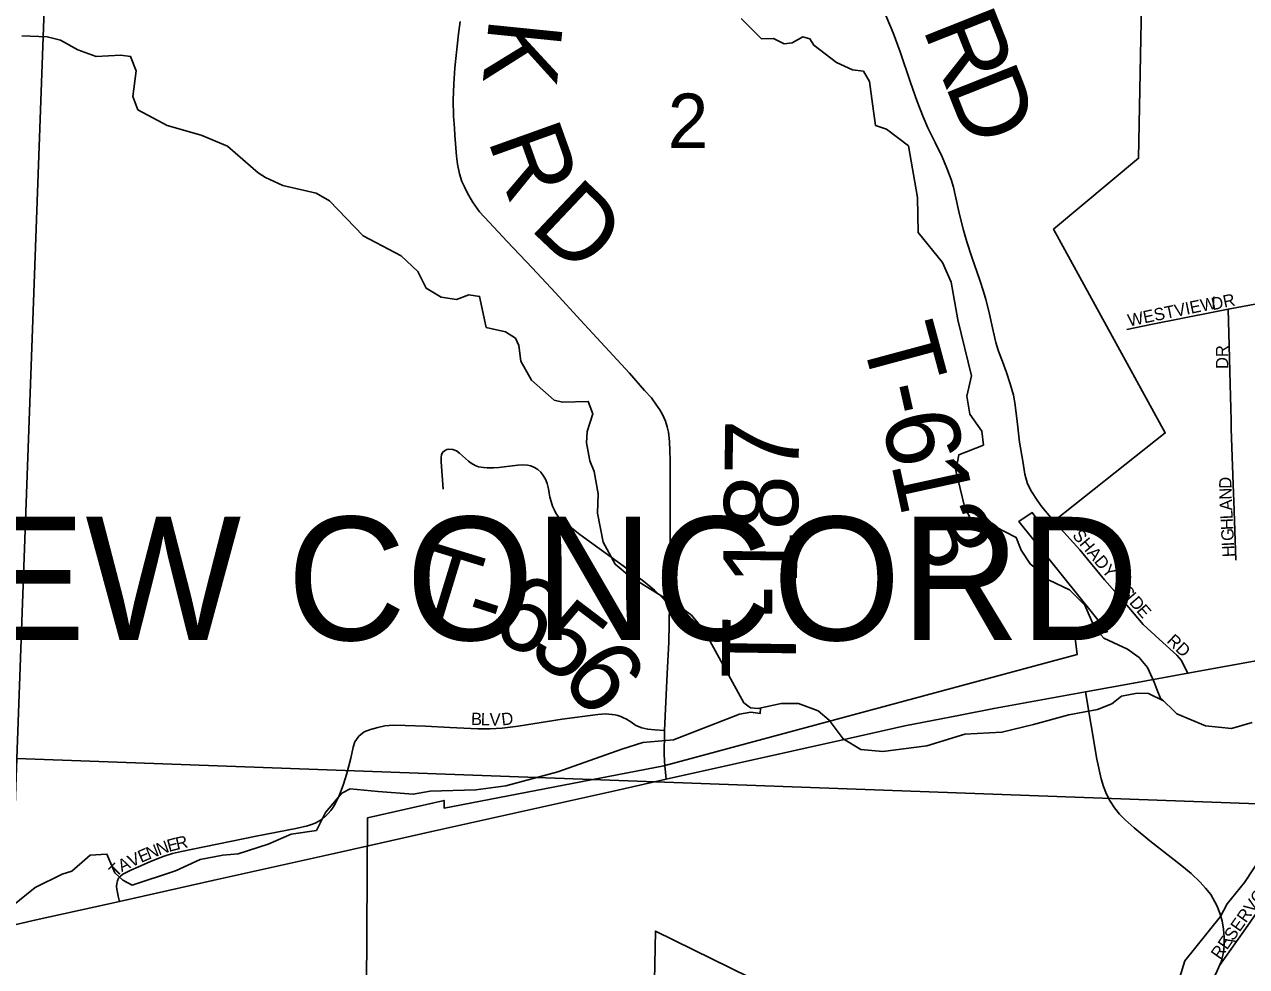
# Model space of a CAD drawing. Extents: x 0 to 34, y 0 to 22.
# Drawn here: x 26.645 to 27.584, y 17.117 to 17.84 of the extents above; entities that cross this region are included whole.
import ezdxf

# ---------------------------------------------------------------- set-up
doc = ezdxf.new("R2010")
doc.units = 0
for name, color, linetype in [('GM_X_City_Street', 7, 'Continuous'), ('GM_X_City_Street_Text', 7, 'Continuous'), ('GM_X_Corporation', 7, 'Continuous'), ('GM_X_Corporation_Text', 7, 'Continuous'), ('GM_X_Minor_River', 7, 'Continuous'), ('GM_X_Section', 7, 'Continuous'), ('GM_X_Section_Text', 7, 'Continuous'), ('GM_X_Township_Road', 7, 'Continuous'), ('GM_X_Township_Road_Text', 7, 'Continuous'), ('GM_X_Township_Subdivision', 7, 'Continuous'), ('GM_X_Township_Subdivision_Text', 7, 'Continuous'), ('GM_X_US_Route', 7, 'Continuous')]:
    doc.layers.add(name, color=color, linetype=linetype)

msp = doc.modelspace()

# ---------------------------------------------------------------- linework, layer by layer
at = {"layer": 'GM_X_City_Street'}
for points in [[(27.56966, 17.62172), (27.58068, 17.62392), (27.60526, 17.62834), (27.63288, 17.63318), (27.64818, 17.63586), (27.6542, 17.63689), (27.68992, 17.64309)], [(27.4918, 17.60613), (27.51017, 17.60988), (27.55923, 17.61963), (27.56966, 17.62172)], [(27.57546, 17.42902), (27.57397, 17.47429), (27.57363, 17.48052), (27.57258, 17.50832), (27.57189, 17.53003), (27.57181, 17.53623), (27.57151, 17.54554), (27.57103, 17.56415), (27.57035, 17.59397), (27.56966, 17.62172)], [(27.53861, 17.34222), (27.5369, 17.34557), (27.53365, 17.35196), (27.53022, 17.35621), (27.51654, 17.3685), (27.50432, 17.37964), (27.4906, 17.39594), (27.47463, 17.41398), (27.45558, 17.43693), (27.43604, 17.45876), (27.43353, 17.46175)], [(27.56653, 17.13793), (27.56654, 17.13955), (27.56598, 17.14584), (27.56483, 17.15205), (27.56316, 17.15814), (27.56084, 17.16405), (27.55787, 17.16964), (27.55614, 17.17229), (27.55228, 17.1773), (27.54804, 17.18196), (27.54119, 17.18843), (27.53396, 17.19442), (27.50936, 17.2136), (27.49734, 17.22344), (27.49044, 17.22965), (27.4862, 17.23411), (27.48233, 17.2389), (27.47895, 17.24399), (27.47618, 17.24946), (27.47396, 17.2552), (27.47217, 17.2611), (27.46863, 17.27622), (27.46011, 17.32793)], [(27.62652, 17.20006), (27.62586, 17.20012), (27.62291, 17.19958), (27.62131, 17.19881), (27.62059, 17.19834), (27.61835, 17.19617), (27.61634, 17.19383), (27.61258, 17.18896), (27.60546, 17.17894), (27.59339, 17.16115), (27.58293, 17.14602), (27.57603, 17.13631)], [(27.56302, 17.11798), (27.56409, 17.12078), (27.565, 17.12383), (27.5657, 17.12693), (27.5662, 17.13006), (27.5665, 17.13322), (27.56653, 17.13793)], [(27.57603, 17.13631), (27.56302, 17.11798)], [(27.56653, 17.13793), (27.57603, 17.13631)], [(27.47295, 16.97658), (27.47573, 16.98116), (27.50327, 17.0227), (27.52697, 17.05934), (27.54391, 17.08549), (27.55559, 17.10394), (27.56024, 17.11211), (27.56302, 17.11798)]]:
    msp.add_lwpolyline(points, dxfattribs=at)
at = {"layer": 'GM_X_Corporation'}
for points in [[(26.90696, 16.92457), (26.90869, 17.23113), (26.9676, 17.24455), (26.96758, 17.23868), (27.13632, 17.27124), (27.45355, 17.35652), (27.45221, 17.36927), (27.4769, 17.37407), (27.40895, 17.45881), (27.41908, 17.4656), (27.42835, 17.45306), (27.5213, 17.52673), (27.43555, 17.68311), (27.50076, 17.73762), (27.50706, 18.06564), (27.60948, 18.06256)], [(26.90696, 16.92457), (26.90869, 17.23113), (26.9676, 17.24455), (26.96758, 17.23868), (27.13632, 17.27124), (27.45355, 17.35652), (27.45221, 17.36927), (27.4769, 17.37407), (27.40895, 17.45881), (27.41908, 17.4656), (27.42835, 17.45306), (27.5213, 17.52673), (27.43555, 17.68311), (27.50076, 17.73762), (27.50706, 18.06564), (27.60948, 18.06256)], [(27.47528, 16.9746), (27.12987, 17.14428), (27.12524, 16.91632)], [(27.47528, 16.9746), (27.12987, 17.14428), (27.12524, 16.91632)]]:
    msp.add_lwpolyline(points, dxfattribs=at)
at = {"layer": 'GM_X_Minor_River'}
for points in [[(27.1957, 17.8449), (27.21128, 17.8294), (27.22037, 17.82946), (27.22873, 17.82534), (27.23479, 17.82614), (27.24309, 17.83074), (27.2484, 17.82926), (27.25147, 17.82435), (27.26898, 17.81118), (27.28113, 17.80557), (27.28947, 17.80448), (27.29407, 17.79654), (27.29646, 17.77949), (27.29884, 17.76282), (27.30719, 17.75983)], [(26.6435, 17.83154), (26.66282, 17.8309), (26.67307, 17.82831), (26.68637, 17.82081), (26.70042, 17.81559), (26.71935, 17.81684), (26.72693, 17.81575), (26.73117, 17.80478), (26.72865, 17.78504), (26.73251, 17.77482), (26.75493, 17.76283), (26.78112, 17.75541), (26.80125, 17.74681), (26.82487, 17.72647), (26.83058, 17.72272), (26.84387, 17.71673), (26.86929, 17.71082), (26.87955, 17.70482), (26.90549, 17.67805), (26.93475, 17.66268), (26.94733, 17.65062), (26.95386, 17.63777), (26.96526, 17.63101), (26.97702, 17.62918), (26.98646, 17.63266), (26.9948, 17.63157), (26.99989, 17.60771), (27.01468, 17.60439), (27.02229, 17.5995), (27.02498, 17.59383), (27.02657, 17.5817), (27.03462, 17.56734), (27.05215, 17.5519), (27.0586, 17.55042), (27.07829, 17.55092), (27.08176, 17.54147), (27.07731, 17.52778), (27.07698, 17.51905), (27.07935, 17.50541), (27.08281, 17.49709), (27.08595, 17.48004), (27.0853, 17.46525), (27.08961, 17.4429), (27.09881, 17.42588), (27.10986, 17.41685), (27.14561, 17.39469), (27.15055, 17.39207), (27.1574, 17.3868), (27.16733, 17.37511), (27.19762, 17.31954), (27.20295, 17.31578), (27.20863, 17.31506), (27.22641, 17.31896), (27.23967, 17.31904), (27.25485, 17.31345), (27.26323, 17.30629), (27.27393, 17.29195), (27.28762, 17.28369), (27.3043, 17.28228)], [(27.30719, 17.75983), (27.32419, 17.74702), (27.33093, 17.70758), (27.33152, 17.68064), (27.35026, 17.65761), (27.35681, 17.64247), (27.36196, 17.61366), (27.37252, 17.57046), (27.36885, 17.55487), (27.37123, 17.54122), (27.38042, 17.528), (27.38164, 17.51738), (27.36275, 17.51003), (27.36057, 17.49787), (27.36722, 17.4702), (27.37261, 17.45923), (27.37792, 17.45851), (27.38472, 17.46084), (27.39045, 17.4548), (27.40681, 17.44657), (27.41067, 17.43673), (27.41757, 17.42615), (27.4252, 17.41975), (27.43207, 17.41372), (27.44766, 17.40624), (27.4595, 17.39456), (27.46721, 17.37677), (27.47409, 17.36923), (27.49234, 17.36063), (27.50111, 17.35424), (27.50761, 17.34669), (27.51262, 17.33534), (27.51494, 17.32928), (27.51725, 17.3236), (27.53023, 17.31117), (27.55228, 17.30183), (27.572, 17.2997), (27.58788, 17.30437)], [(27.3043, 17.28228), (27.3383, 17.28664), (27.36741, 17.29558), (27.39582, 17.29692), (27.42003, 17.30279), (27.44725, 17.3102), (27.4692, 17.31453), (27.48015, 17.31878), (27.48769, 17.32453), (27.4998, 17.3269), (27.50852, 17.32658), (27.52001, 17.32097)], [(27.21042, 17.31545), (27.21017, 17.31127), (27.20297, 17.31236), (27.19427, 17.31079), (27.14365, 17.29113), (27.12017, 17.28909), (27.10392, 17.28406), (27.0548, 17.26668), (27.0151, 17.25581), (26.99201, 17.25263), (26.95679, 17.25165), (26.94393, 17.2493), (26.91703, 17.25141), (26.89542, 17.25354), (26.88901, 17.25009), (26.87661, 17.23522), (26.8695, 17.22152), (26.8502, 17.21875), (26.83245, 17.21105), (26.8094, 17.2037), (26.79766, 17.20249), (26.78026, 17.19934), (26.76138, 17.1905), (26.72812, 17.17967), (26.7209, 17.18342), (26.7148, 17.18907), (26.70865, 17.20345), (26.69577, 17.20261), (26.68184, 17.19038), (26.67428, 17.18806), (26.65352, 17.17769), (26.63506, 17.16278)], [(27.53253, 17.10885), (27.53622, 17.1214), (27.56363, 17.15538), (27.56886, 17.16529), (27.58199, 17.18171), (27.59585, 17.20269), (27.6055, 17.22971), (27.61059, 17.25784), (27.60936, 17.27073), (27.61283, 17.29732)]]:
    msp.add_lwpolyline(points, dxfattribs=at)
at = {"layer": 'GM_X_Section'}
for points in [[(26.67748, 18.31474), (26.63943, 17.27671), (26.13693, 17.28272), (26.13573, 17.24141), (25.63163, 17.25763), (25.68285, 18.35754)], [(26.67748, 18.31474), (27.6773, 18.28453), (27.62712, 17.24067), (26.63943, 17.27671)]]:
    msp.add_lwpolyline(points, close=True, dxfattribs=at)
msp.add_lwpolyline([(27.10364, 16.25426), (26.60351, 16.27226), (26.63943, 17.27671), (27.62712, 17.24067), (27.60079, 16.42084)], dxfattribs=at)
at = {"layer": 'GM_X_Township_Road'}
for points in [[(27.43353, 17.46175), (27.4265, 17.47012), (27.42279, 17.47504), (27.41869, 17.4818), (27.41562, 17.48774), (27.41346, 17.4952), (27.41193, 17.50516), (27.40933, 17.51963), (27.40824, 17.52877), (27.40725, 17.53784), (27.40572, 17.54975), (27.40463, 17.55565), (27.40225, 17.56437), (27.39936, 17.573), (27.39622, 17.58161), (27.39409, 17.58737), (27.39307, 17.59028), (27.3913, 17.59621), (27.38905, 17.60521), (27.3857, 17.62027), (27.38344, 17.62926), (27.38175, 17.63522), (27.37884, 17.64407), (27.37265, 17.66168), (27.36886, 17.67352), (27.36629, 17.68246), (27.36333, 17.69446), (27.35997, 17.70947), (27.35862, 17.71546), (27.35683, 17.72135), (27.35362, 17.73005), (27.34994, 17.7386), (27.34451, 17.74979), (27.33909, 17.76099), (27.33535, 17.76952), (27.33089, 17.78112), (27.32568, 17.79576), (27.31773, 17.81933), (27.31225, 17.83388), (27.30267, 17.85684)], [(27.14062, 17.39458), (27.14127, 17.43869), (27.14118, 17.50049), (27.14118, 17.50544), (27.14091, 17.51326), (27.14055, 17.52028), (27.13975, 17.52737), (27.13895, 17.53149), (27.13746, 17.53583), (27.13552, 17.54029), (27.13311, 17.54441), (27.13063, 17.54812), (27.12671, 17.55363), (27.12146, 17.55928), (27.10995, 17.57261), (27.07219, 17.6134), (27.05321, 17.6344), (27.03523, 17.65358), (27.01605, 17.67358), (27.00212, 17.68852), (26.99465, 17.69659), (26.98939, 17.70427), (26.98556, 17.71073), (26.98314, 17.71578), (26.98114, 17.71987), (26.97952, 17.72553), (26.97797, 17.73294), (26.97715, 17.73908), (26.97574, 17.7552), (26.97556, 17.76071), (26.97486, 17.76994), (26.97462, 17.78227), (26.97499, 17.79461), (26.97591, 17.80697), (26.97865, 17.83314), (26.9798, 17.84247)], [(26.96699, 17.48354), (26.96534, 17.50442), (26.96534, 17.50793), (26.96553, 17.50988), (26.96641, 17.51183), (26.96797, 17.5131), (26.96972, 17.51389), (26.97117, 17.5142), (26.97423, 17.51397), (26.97701, 17.51288), (26.97947, 17.51113), (26.98182, 17.5091), (26.98406, 17.50706), (26.98621, 17.50501), (26.98846, 17.50345), (26.99148, 17.50179), (26.99412, 17.50071), (26.99773, 17.50013), (27.00075, 17.49984), (27.00543, 17.49993), (27.00969, 17.50026), (27.02426, 17.50198), (27.02816, 17.50232), (27.03158, 17.50198), (27.03423, 17.50148), (27.03707, 17.5003), (27.03965, 17.49862), (27.04189, 17.49649), (27.04373, 17.49403), (27.04543, 17.49115), (27.0468, 17.48803), (27.04777, 17.48374), (27.04836, 17.48044), (27.04885, 17.4774), (27.04974, 17.4741), (27.05076, 17.47061), (27.05199, 17.46786), (27.05343, 17.46516), (27.05512, 17.46259), (27.05721, 17.46034), (27.05953, 17.45833), (27.06439, 17.45453), (27.07176, 17.44887), (27.08676, 17.43797), (27.10515, 17.42473), (27.12075, 17.41291), (27.12901, 17.40605), (27.13395, 17.40133), (27.13865, 17.39651), (27.14062, 17.39458)], [(27.13681, 17.29823), (27.13746, 17.31485), (27.1389, 17.34174), (27.14002, 17.36598), (27.14062, 17.39458)], [(27.1381, 17.26087), (27.13714, 17.27151), (27.13687, 17.2746), (27.13659, 17.28078), (27.13673, 17.29628), (27.13681, 17.29823)]]:
    msp.add_lwpolyline(points, dxfattribs=at)
at = {"layer": 'GM_X_Township_Subdivision'}
for points in [[(26.92204, 17.30182), (26.92879, 17.30228), (26.93778, 17.30202), (26.95328, 17.30151), (26.97188, 17.30055), (26.9936, 17.29968), (27.0029, 17.29966), (27.01219, 17.3002), (27.02451, 17.30171), (27.05826, 17.30691), (27.08563, 17.31064), (27.08873, 17.31088), (27.09139, 17.31103), (27.09399, 17.31081), (27.09646, 17.31069), (27.09882, 17.31024), (27.10098, 17.30975), (27.10324, 17.30901), (27.10531, 17.30813), (27.10757, 17.30702), (27.11097, 17.30482), (27.11476, 17.30222), (27.11935, 17.30023), (27.12394, 17.29923), (27.12948, 17.29869), (27.13681, 17.29823)], [(26.71827, 17.16704), (26.71802, 17.16809), (26.71732, 17.17106), (26.71673, 17.17387), (26.7164, 17.17636), (26.71619, 17.17861), (26.71635, 17.18095), (26.71682, 17.18284), (26.71772, 17.18483), (26.71907, 17.18636), (26.72094, 17.18787), (26.72339, 17.18924), (26.7272, 17.19116), (26.73289, 17.19358), (26.74161, 17.19748), (26.74731, 17.19986), (26.75265, 17.20181), (26.75899, 17.20375), (26.76598, 17.20539), (26.77456, 17.20726), (26.82323, 17.21718), (26.85373, 17.22298), (26.86282, 17.22507), (26.86577, 17.22602), (26.86864, 17.2272), (26.8714, 17.2286), (26.87398, 17.2303), (26.87637, 17.23226), (26.87857, 17.23445), (26.88058, 17.23682), (26.8824, 17.23934), (26.88404, 17.24197), (26.88674, 17.24755), (26.88998, 17.25629), (26.89278, 17.26517), (26.896, 17.27714), (26.89778, 17.28556), (26.89913, 17.2896), (26.90209, 17.29391), (26.90614, 17.29715), (26.91111, 17.299), (26.91666, 17.30066), (26.92204, 17.30182)]]:
    msp.add_lwpolyline(points, dxfattribs=at)
at = {"layer": 'GM_X_US_Route'}
for points in [[(27.46011, 17.32793), (27.49694, 17.33455), (27.53861, 17.34222), (27.59798, 17.35315), (27.6307, 17.35887), (27.66276, 17.36448), (27.69723, 17.36996), (27.71118, 17.37193), (27.71722, 17.37269), (27.73328, 17.3747), (27.76143, 17.37765), (27.78511, 17.37987)], [(26.91061, 17.21004), (26.95812, 17.22087), (27.10086, 17.25252), (27.1381, 17.26087), (27.19197, 17.27294), (27.27696, 17.29189), (27.32127, 17.30176), (27.36387, 17.31017), (27.3896, 17.31518), (27.41488, 17.31986), (27.46011, 17.32793)], [(26.17158, 17.01927), (26.18259, 17.02497), (26.20211, 17.03432), (26.22188, 17.04315), (26.24191, 17.05141), (26.26211, 17.05917), (26.27964, 17.06521), (26.30113, 17.07186), (26.32136, 17.07752), (26.3405, 17.08238), (26.35997, 17.08704), (26.42396, 17.10133), (26.47555, 17.11285), (26.61508, 17.144), (26.62241, 17.14564), (26.64018, 17.14963), (26.65449, 17.15284), (26.70909, 17.16497), (26.71827, 17.16704), (26.79102, 17.1835), (26.88323, 17.2038), (26.91061, 17.21004)]]:
    msp.add_lwpolyline(points, dxfattribs=at)

# ---------------------------------------------------------------- texts
at = {"layer": 'GM_X_City_Street_Text'}
for s, rotation, p in [('WESTVIEW', 11.61133, (27.49353, 17.60841)), ('DR', 11.88173, (27.55767, 17.62091)), ('DR', 90, (27.56961, 17.57583)), ('D', 90.08745, (27.57212, 17.4839)), ('N', 91.83634, (27.57238, 17.47564)), ('A', 92.88643, (27.5728, 17.46737)), ('L', 92.91662, (27.57314, 17.46071)), ('SHADY', 309.9569, (27.44942, 17.44781)), ('H', 92.88643, (27.57356, 17.45238)), ('G', 92.88643, (27.57398, 17.44406)), ('I', 92.88643, (27.57419, 17.4399)), ('H', 92.88643, (27.57461, 17.43158)), ('S', 310.86208, (27.48608, 17.40449)), ('I', 310.93675, (27.49045, 17.39943)), ('D', 310.88576, (27.49318, 17.39629)), ('E', 310.86208, (27.49863, 17.38999)), ('RD', 317.1199, (27.52176, 17.36631)), ('RESERVOIR', 54.71538, (27.56327, 17.12187))]:
    msp.add_text(s, height=0.00947, rotation=rotation, dxfattribs=at).set_placement(p)
at = {"layer": 'GM_X_Corporation_Text'}
msp.add_text('NEW CONCORD', height=0.094697, rotation=0.00001, dxfattribs=at).set_placement((26.5163, 17.36764))
at = {"layer": 'GM_X_Section_Text'}
msp.add_text('2', height=0.04186, rotation=0.00001, dxfattribs=at).set_placement((27.1393, 17.74537))
at = {"layer": 'GM_X_Township_Road_Text'}
for s, height, rotation, p in [('R', 0.05682, 291.70865, (27.3346, 17.83755)), ('K', 0.05682, 264.22017, (27.00237, 17.84639)), ('D', 0.05682, 291.63095, (27.35186, 17.79421)), ('R', 0.05682, 289.70023, (27.00075, 17.75198)), ('D', 0.05682, 316.58708, (27.03225, 17.68388)), ('T', 0.05682, 285.06117, (27.28733, 17.60147)), ('-', 0.05682, 282.70324, (27.29823, 17.56103)), ('6', 0.05682, 281.74877, (27.3033, 17.53851)), ('T-187', 0.056818, 89.18806, (27.23745, 17.33784)), ('1', 0.05682, 282.34207, (27.31056, 17.50361)), ('3', 0.05682, 297.10734, (27.32342, 17.45443)), ('T', 0.05682, 342.9896, (26.94016, 17.38899)), ('6', 0.05682, 335.99102, (27.00128, 17.37002)), ('-', 0.05682, 342.06859, (26.98057, 17.37663)), ('5', 0.05682, 322.73252, (27.03027, 17.35755)), ('6', 0.05682, 308.38024, (27.05544, 17.33898))]:
    msp.add_text(s, height=height, rotation=rotation, dxfattribs=at).set_placement(p)
at = {"layer": 'GM_X_Township_Subdivision_Text'}
for s, rotation, p in [('B', 358.15396, (26.98812, 17.30261)), ('L', 358.14182, (26.99561, 17.30237)), ('V', 359.12655, (27.00245, 17.30215)), ('D', 6.72933, (27.01212, 17.30209)), ('E', 23.67945, (26.73497, 17.19653)), ('N', 21.39541, (26.74098, 17.19917)), ('N', 20.19787, (26.74869, 17.20219)), ('E', 14.83114, (26.75628, 17.20499)), ('R', 12.83441, (26.76264, 17.20668)), ('A', 26.42823, (26.72003, 17.18941)), ('V', 24.49278, (26.72741, 17.19309)), ('T', 45.27044, (26.716, 17.18516))]:
    msp.add_text(s, height=0.00947, rotation=rotation, dxfattribs=at).set_placement(p)

doc.saveas('drawing.dxf')
